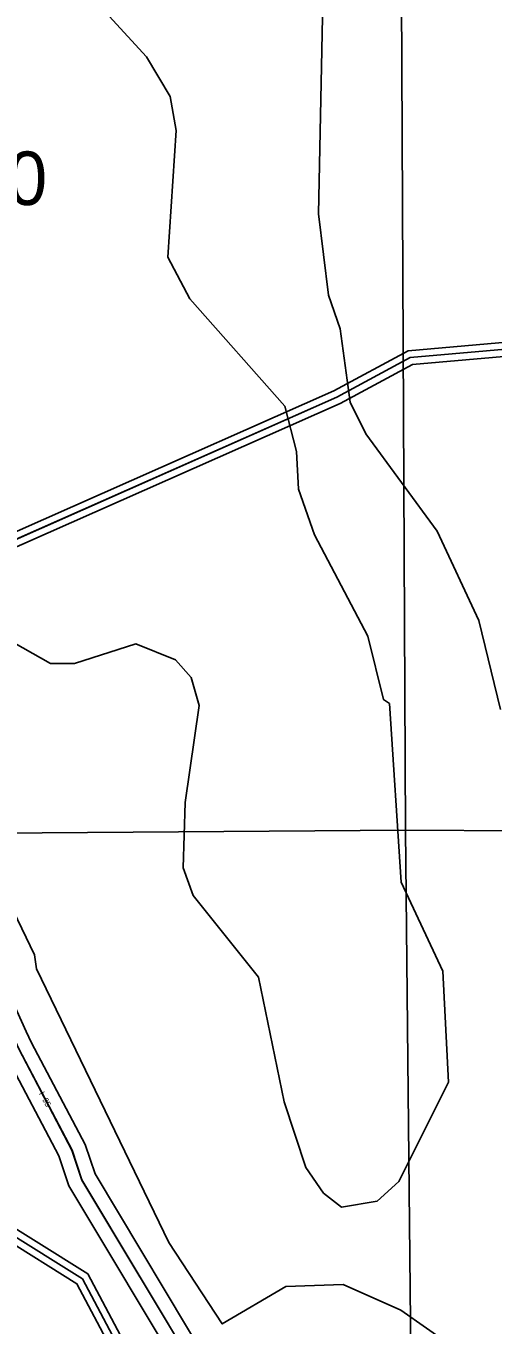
# Model space of a CAD drawing. Extents: x 457167 to 656239, y 1787309 to 1969297.
# Drawn here: x 578095 to 580059, y 1911582 to 1917044 of the extents above; entities that cross this region are included whole.
import ezdxf

# ---------------------------------------------------------------- set-up
doc = ezdxf.new("R2010")
doc.units = 0
for name, color, linetype in [('Level 1', 7, 'Continuous'), ('Level 13', 7, 'Continuous'), ('Level 14', 7, 'Continuous'), ('Level 2', 7, 'Continuous'), ('Level 31', 7, 'Continuous'), ('Level 32', 7, 'Continuous'), ('Level 34', 7, 'Continuous'), ('Level 7', 7, 'Continuous'), ('Level 8', 7, 'Continuous')]:
    doc.layers.add(name, color=color, linetype=linetype)

msp = doc.modelspace()

# ---------------------------------------------------------------- linework, layer by layer
at = {"layer": 'Level 1'}
for p, q in [((579665.428, 1918947.414), (579691.072, 1913661.836)), ((579691.072, 1913661.836), (576783.949, 1913641.498)), ((579691.072, 1913661.836), (579742.085, 1908632.671)), ((581969.053, 1913654.676), (579691.072, 1913661.836))]:
    msp.add_line(p, q, dxfattribs=at)
at = {"layer": 'Level 13'}
for points in [[(578330.566, 1912191.644), (578288.875, 1912316.826), (578064.429, 1912742.398), (578041.967, 1912791.538)], [(580924.16, 1907685.826), (580167.749, 1908987.76), (580043.06, 1909254.566), (579826.985, 1909596.836), (579818.524, 1909655.037), (579585.659, 1910022.435), (579569.285, 1910097.379), (579444.398, 1910264.186), (578820.866, 1911373.871), (578330.566, 1912191.644)]]:
    msp.add_lwpolyline(points, dxfattribs=at)
at = {"layer": 'Level 14'}
msp.add_line((578096.558, 1912816.438), (577354.396, 1914443.502), dxfattribs=at)
for points in [[(578385.414, 1912216.85), (578344.244, 1912340.459), (578118.293, 1912768.887), (578096.537, 1912816.482)], [(578275.721, 1912166.436), (578233.505, 1912293.192), (578010.565, 1912715.91), (577987.398, 1912766.594)], [(580976.04, 1907715.967), (580220.974, 1909015.588), (580095.816, 1909283.397), (579884.528, 1909618.086), (579876.058, 1909676.342), (579642.014, 1910045.601), (579625.124, 1910122.912), (579494.782, 1910297.004), (578872.76, 1911404.001), (578385.413, 1912216.85)], [(580872.28, 1907655.684), (580114.525, 1908959.931), (579990.304, 1909225.736), (579769.444, 1909575.588), (579760.99, 1909633.732), (579529.304, 1909999.269), (579513.448, 1910071.846), (579394.013, 1910231.37), (578768.972, 1911343.741), (578275.722, 1912166.436)]]:
    msp.add_lwpolyline(points, dxfattribs=at)
at = {"layer": 'Level 31'}
for points in [[(577450.556, 1914619.012), (579402.759, 1915482.919), (579711.372, 1915649.191), (581203.721, 1915779.952), (581470.875, 1915879.776)], [(577672.328, 1912188.674), (578332.237, 1911776.36), (578788.125, 1910915.386)]]:
    msp.add_lwpolyline(points, dxfattribs=at)
at = {"layer": 'Level 32'}
for points in [[(577439.424, 1914646.891), (579389.554, 1915509.883), (579702.589, 1915678.537), (581197.039, 1915809.483), (581438.852, 1915899.836)], [(577461.691, 1914591.131), (579415.964, 1915455.955), (579720.154, 1915619.845), (581210.403, 1915750.421), (581457.444, 1915842.73)], [(577682.049, 1912147.226), (578309.499, 1911755.191), (578750.743, 1910921.875)], [(577713.488, 1912198.332), (578354.974, 1911797.528), (578814.638, 1910929.425)]]:
    msp.add_lwpolyline(points, dxfattribs=at)
at = {"layer": 'Level 7'}
for points in [[(580090.662, 1914169.346), (579999.386, 1914544.576), (579824.709, 1914919.913), (579525.019, 1915328.721), (579458.467, 1915462.165), (579417.143, 1915770.641), (579367.25, 1915912.425), (579325.924, 1916254.253), (579361.182, 1918046.536)], [(578351.59, 1917188.971), (578601.387, 1916913.605), (578701.22, 1916746.781), (578726.103, 1916605.038), (578692.179, 1916071.535), (578783.713, 1915896.381), (579183.364, 1915445.792), (579233.187, 1915253.988), (579241.329, 1915095.595), (579307.833, 1914903.791)], [(579307.833, 1914903.791), (579532.451, 1914478.381), (579598.885, 1914211.555), (579623.856, 1914194.845), (579673.067, 1913444.537), (579847.744, 1913069.209), (579872.26, 1912602.338), (579663.403, 1912185.746), (579571.643, 1912102.484), (579421.551, 1912077.633), (579346.589, 1912136.054), (579271.667, 1912244.526), (579180.253, 1912519.722), (579072.434, 1913045.014), (578797.726, 1913387.101), (578756.144, 1913503.874), (578764.77, 1913778.941), (578823.576, 1914187.361), (578790.364, 1914304.133), (578723.742, 1914379.225), (578557.079, 1914446.076), (578298.557, 1914363.012), (578198.525, 1914363.111), (577856.959, 1914555.204)], [(577523.316, 1914397.169), (578130.53, 1913137.731), (578138.801, 1913079.371), (578696.134, 1911928.336), (578920.861, 1911586.318), (579187.783, 1911744.414), (579429.536, 1911752.485), (579671.19, 1911643.854), (579887.765, 1911493.571)]]:
    msp.add_lwpolyline(points, dxfattribs=at)
at = {"layer": 'Level 8'}
msp.add_lwpolyline([(580167.522, 1908987.372), (580043.517, 1909254.378), (579826.509, 1909596.386), (579818.509, 1909655.386), (579585.501, 1910022.394), (579569.499, 1910097.396), (579444.496, 1910264.399), (578820.473, 1911373.423), (578330.455, 1912191.44), (578288.454, 1912316.443), (578064.445, 1912742.451), (578042.444, 1912791.453), (577299.413, 1914418.488), (577242.41, 1914544.491), (577450.412, 1914619.494), (579402.426, 1915482.525), (579711.428, 1915649.531), (581203.445, 1915779.541)], dxfattribs=at)

# ---------------------------------------------------------------- texts
at = {"layer": 'Level 2'}
msp.add_text('26-10-30', height=225, dxfattribs=at).set_placement((576980.019, 1916290.852))
at = {"layer": 'Level 34'}
msp.add_text('I- 95', height=25, rotation=297.806658, dxfattribs=at).set_placement((578148.92, 1912555.401))

doc.saveas('drawing.dxf')
